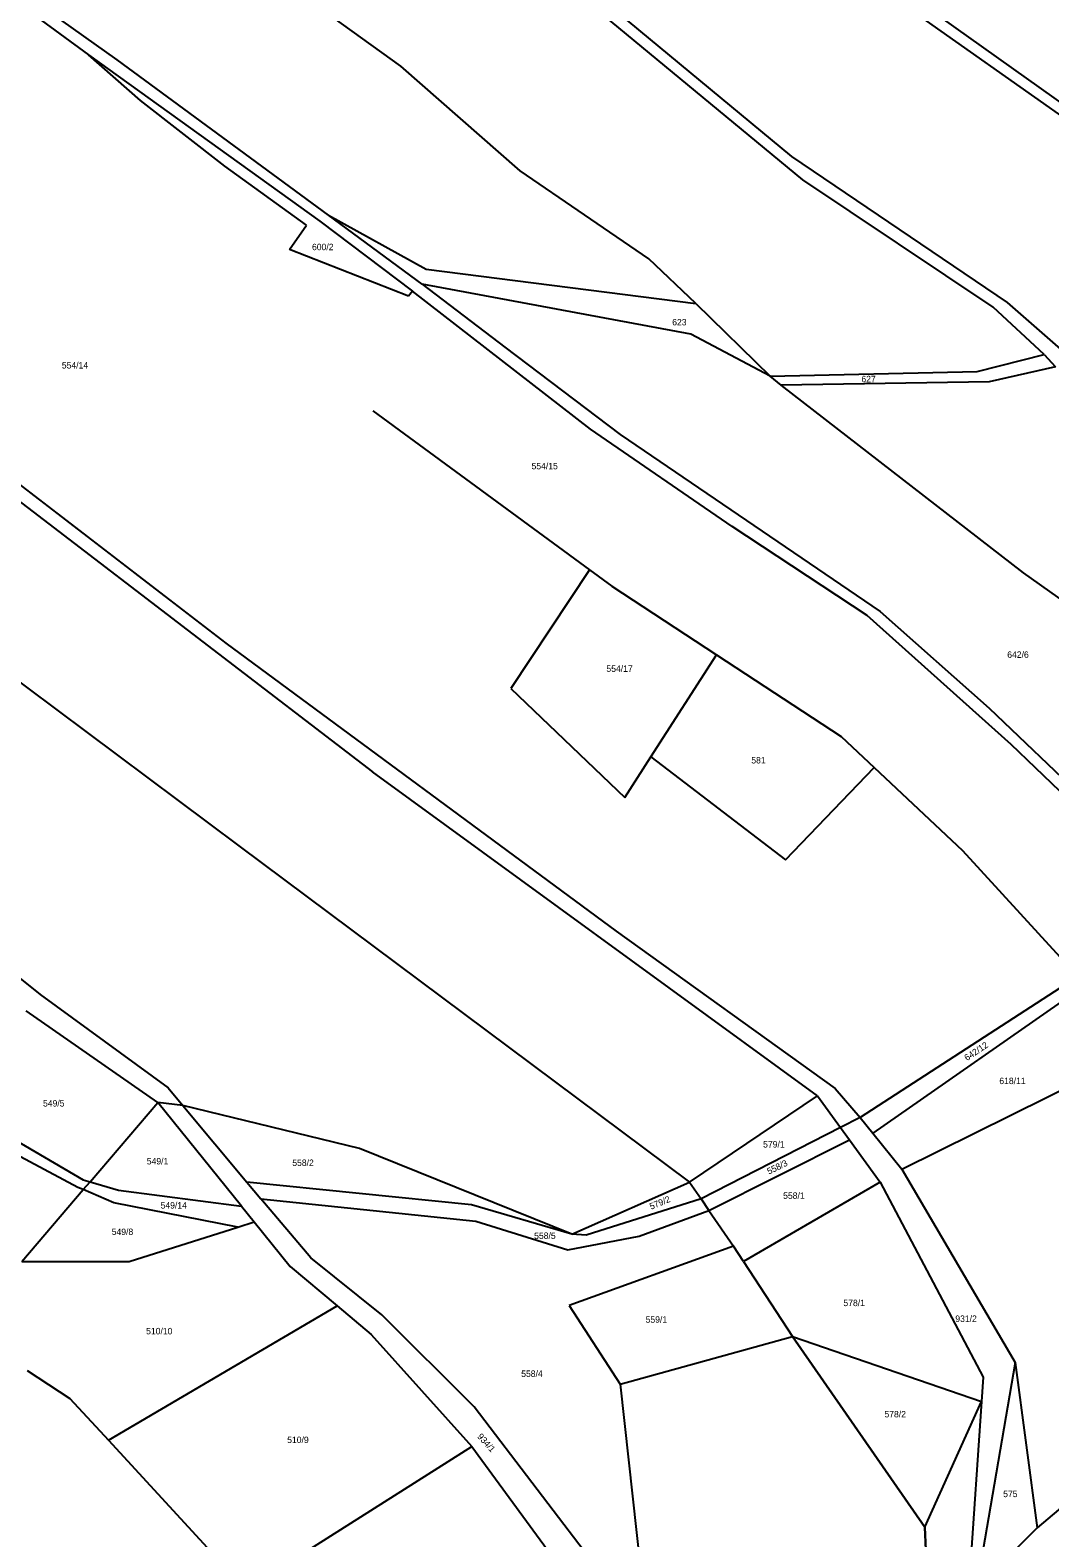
# Model space of a CAD drawing. Extents: x -593358 to -590116, y -1072518 to -1068420.
# Drawn here: x -591318.1 to -591048.4, y -1071622.8 to -1071223.8 of the extents above; entities that cross this region are included whole.
import ezdxf

# ---------------------------------------------------------------- set-up
doc = ezdxf.new("R2010")
doc.units = 0
for name, color, linetype in [('lesy', 7, 'Continuous'), ('Parcela KN', 7, 'Continuous'), ('Parcela ZE', 7, 'Continuous'), ('Parcelní číslo', 7, 'Continuous')]:
    doc.layers.add(name, color=color, linetype=linetype)

msp = doc.modelspace()

# ---------------------------------------------------------------- linework, layer by layer
at = {"layer": 'lesy'}
msp.add_lwpolyline([(-591129.41, -1071549.64), (-591116.49, -1071569.55), (-591081.49, -1071619.93), (-591080.6, -1071640.12), (-591074.27, -1071656.72), (-591050.09, -1071672.8)], dxfattribs=at)
at = {"layer": 'Parcela KN'}
for p, q in [((-591295.06, -1071231.67), (-591426.56, -1071138.15)), ((-591316.46, -1071220.2), (-591302.62, -1071230.31)), ((-591288.86, -1071242.43), (-591302.62, -1071230.31)), ((-591302.62, -1071230.31), (-591241.43, -1071274.4)), ((-591239.21, -1071272.82), (-591295.06, -1071231.67)), ((-591266.55, -1071259.85), (-591288.86, -1071242.43)), ((-591244.96, -1071275.42), (-591266.55, -1071259.85)), ((-591249.53, -1071281.83), (-591244.96, -1071275.42)), ((-591241.43, -1071274.4), (-591216.95, -1071292.85)), ((-591214.39, -1071291), (-591239.21, -1071272.82)), ((-591239.21, -1071272.82), (-591213.35, -1071287.04)), ((-591218.05, -1071294.25), (-591249.53, -1071281.83)), ((-591213.35, -1071287.04), (-591142.01, -1071296.18)), ((-591214.39, -1071291), (-591192.53, -1071307.71)), ((-591143.32, -1071304.27), (-591214.39, -1071291)), ((-591216.95, -1071292.85), (-591218.05, -1071294.25)), ((-591169.9, -1071329.38), (-591216.95, -1071292.85)), ((-591142.01, -1071296.18), (-591122.34, -1071315.38)), ((-591192.53, -1071307.71), (-591162.08, -1071330.84)), ((-591122.34, -1071315.38), (-591143.32, -1071304.27)), ((-591067.64, -1071314.19), (-591049.88, -1071309.61)), ((-591049.88, -1071309.61), (-591046.94, -1071312.91)), ((-591122.34, -1071315.38), (-591067.64, -1071314.19)), ((-591119.47, -1071317.8), (-591122.34, -1071315.38)), ((-591046.94, -1071312.91), (-591064.41, -1071316.85)), ((-591064.41, -1071316.85), (-591119.47, -1071317.8)), ((-591132.39, -1071355.14), (-591169.9, -1071329.38)), ((-591162.08, -1071330.84), (-591093.32, -1071377.7)), ((-591096.76, -1071378.69), (-591132.39, -1071355.14)), ((-591058.67, -1071412.83), (-591096.76, -1071378.69)), ((-591093.32, -1071377.7), (-591064.44, -1071403.25)), ((-591064.44, -1071403.25), (-590999.61, -1071465.32)), ((-591002.01, -1071467.25), (-591058.67, -1071412.83)), ((-591040.99, -1071474.28), (-591098.56, -1071511.54)), ((-591039.55, -1071476.88), (-591095.19, -1071515.74)), ((-591284.34, -1071507.63), (-591319.16, -1071483.34)), ((-591305.47, -1071530.05), (-591366.89, -1071497.44)), ((-591277.68, -1071508.42), (-591284.34, -1071507.63)), ((-591262.21, -1071535), (-591284.34, -1071507.63)), ((-591143.7, -1071528.67), (-591109.83, -1071505.86)), ((-591109.83, -1071505.86), (-591103.79, -1071514.24)), ((-591338.84, -1071507.71), (-591304.1, -1071528.01)), ((-591231.01, -1071519.76), (-591277.68, -1071508.42)), ((-591277.68, -1071508.42), (-591260.75, -1071528.68)), ((-591098.56, -1071511.54), (-591103.79, -1071514.24)), ((-591098.56, -1071511.54), (-591095.19, -1071515.74)), ((-591103.79, -1071514.24), (-591140.65, -1071533.12)), ((-591103.79, -1071514.24), (-591101.41, -1071517.51)), ((-591138.55, -1071536.14), (-591101.41, -1071517.51)), ((-591101.41, -1071517.51), (-591093.27, -1071528.7)), ((-591095.19, -1071515.74), (-591087.56, -1071525.25)), ((-591174.8, -1071542.41), (-591231.01, -1071519.76)), ((-591087.56, -1071525.25), (-591057.55, -1071576.38)), ((-591304.05, -1071530.65), (-591305.47, -1071530.05)), ((-591304.1, -1071528.01), (-591302.25, -1071528.55)), ((-591295.93, -1071534.12), (-591304.05, -1071530.65)), ((-591302.25, -1071528.55), (-591294.72, -1071530.78)), ((-591294.72, -1071530.78), (-591262.21, -1071535)), ((-591201.39, -1071534.67), (-591260.75, -1071528.68)), ((-591260.75, -1071528.68), (-591257.09, -1071533.05)), ((-591174.8, -1071542.41), (-591143.7, -1071528.67)), ((-591093.27, -1071528.7), (-591129.41, -1071549.64)), ((-591093.27, -1071528.7), (-591066.07, -1071580.27)), ((-591263.17, -1071540.57), (-591295.93, -1071534.12)), ((-591262.21, -1071535), (-591258.83, -1071539.2)), ((-591243.84, -1071548.69), (-591257.09, -1071533.05)), ((-591257.09, -1071533.05), (-591200.23, -1071538.99)), ((-591174.8, -1071542.41), (-591201.39, -1071534.67)), ((-591140.65, -1071533.12), (-591171.07, -1071542.73)), ((-591263.17, -1071540.57), (-591258.83, -1071539.2)), ((-591258.83, -1071539.2), (-591249.32, -1071551.02)), ((-591200.23, -1071538.99), (-591175.89, -1071546.61)), ((-591157.04, -1071542.95), (-591138.55, -1071536.14)), ((-591291.88, -1071549.63), (-591263.17, -1071540.57)), ((-591175.89, -1071546.61), (-591157.04, -1071542.95)), ((-591171.07, -1071542.73), (-591174.8, -1071542.41)), ((-591132.05, -1071545.6), (-591175.49, -1071561.31)), ((-591129.41, -1071549.64), (-591132.05, -1071545.6)), ((-591320.29, -1071549.62), (-591291.88, -1071549.63)), ((-591249.32, -1071551.02), (-591236.9, -1071561.42)), ((-591225.05, -1071563.81), (-591243.84, -1071548.69)), ((-591129.41, -1071549.64), (-591116.49, -1071569.55)), ((-590978.58, -1071557.78), (-591051.73, -1071620.17)), ((-591236.9, -1071561.42), (-591227.85, -1071569)), ((-591175.49, -1071561.31), (-591162.02, -1071582.15)), ((-591200.64, -1071588.13), (-591225.05, -1071563.81)), ((-591227.85, -1071569), (-591201.27, -1071598.58)), ((-591162.02, -1071582.15), (-591116.49, -1071569.55)), ((-591116.49, -1071569.55), (-591066.5, -1071586.69)), ((-591081.49, -1071619.93), (-591116.49, -1071569.55)), ((-591057.55, -1071576.38), (-591067.34, -1071633.4)), ((-591057.55, -1071576.38), (-591051.73, -1071620.17)), ((-591162.02, -1071582.15), (-591156.54, -1071631.79)), ((-591066.07, -1071580.27), (-591066.5, -1071586.69)), ((-591081.49, -1071619.93), (-591066.5, -1071586.69)), ((-591066.5, -1071586.69), (-591071.03, -1071653.67)), ((-591154.73, -1071648.38), (-591200.64, -1071588.13)), ((-591201.27, -1071598.58), (-591172.76, -1071637.59)), ((-591080.6, -1071640.12), (-591081.49, -1071619.93)), ((-591051.73, -1071620.17), (-591065.88, -1071634.25))]:
    msp.add_line(p, q, dxfattribs=at)
at = {"layer": 'Parcela ZE'}
for p, q in [((-591220.06, -1071233.35), (-591352.83, -1071137.47)), ((-591195.09, -1071192.29), (-591116.7, -1071257.23)), ((-591113.72, -1071263.44), (-591194.82, -1071196.39)), ((-591104.41, -1071204.86), (-591016.95, -1071266.67)), ((-591016.38, -1071263.81), (-591096.58, -1071206.61)), ((-591188.46, -1071261.08), (-591220.06, -1071233.35)), ((-591116.7, -1071257.23), (-591059.73, -1071295.92)), ((-591154.46, -1071284.37), (-591188.46, -1071261.08)), ((-591063.41, -1071297.16), (-591113.72, -1071263.44)), ((-591142.01, -1071296.18), (-591154.46, -1071284.37)), ((-591059.73, -1071295.92), (-591044.16, -1071309.49)), ((-591049.88, -1071309.61), (-591063.41, -1071297.16)), ((-591362.5, -1071312.09), (-591266.35, -1071386)), ((-591360.73, -1071318.27), (-591317.27, -1071351.25)), ((-591055.39, -1071367.39), (-591119.47, -1071317.8)), ((-591227.42, -1071324.56), (-591170.19, -1071366.63)), ((-591382.66, -1071350.21), (-591262.87, -1071439.67)), ((-591317.27, -1071351.25), (-591227.56, -1071420.07)), ((-591170.19, -1071366.63), (-591191, -1071398.03)), ((-591170.19, -1071366.63), (-591164.27, -1071370.98)), ((-591028.91, -1071386.21), (-591055.39, -1071367.39)), ((-591164.27, -1071370.98), (-591136.59, -1071389.1)), ((-591266.35, -1071386), (-591163.09, -1071462.29)), ((-591153.95, -1071416.15), (-591136.59, -1071389.1)), ((-591136.59, -1071389.1), (-591103.56, -1071410.73)), ((-591191, -1071398.03), (-591160.85, -1071426.9)), ((-591103.56, -1071410.73), (-591094.85, -1071418.94)), ((-591393.82, -1071416.4), (-591315.39, -1071478.99)), ((-591160.85, -1071426.9), (-591153.95, -1071416.15)), ((-591153.95, -1071416.15), (-591118.33, -1071443.4)), ((-591118.33, -1071443.4), (-591094.85, -1071418.94)), ((-591094.85, -1071418.94), (-591071.54, -1071440.92)), ((-591109.83, -1071505.86), (-591227.56, -1071420.07)), ((-591262.87, -1071439.67), (-591143.7, -1071528.67)), ((-591071.54, -1071440.92), (-591040.99, -1071474.28)), ((-591163.09, -1071462.29), (-591105.16, -1071503.86)), ((-591315.39, -1071478.99), (-591281.62, -1071503.75)), ((-591087.56, -1071525.25), (-591026.5, -1071494.92)), ((-591302.25, -1071528.55), (-591284.34, -1071507.63)), ((-591281.62, -1071503.75), (-591277.68, -1071508.42)), ((-591105.16, -1071503.86), (-591098.56, -1071511.54)), ((-591320.29, -1071549.62), (-591304.05, -1071530.65)), ((-591304.05, -1071530.65), (-591302.25, -1071528.55)), ((-591143.7, -1071528.67), (-591140.65, -1071533.12)), ((-591140.65, -1071533.12), (-591138.55, -1071536.14)), ((-591138.55, -1071536.14), (-591132.05, -1071545.6)), ((-591297.38, -1071596.97), (-591236.9, -1071561.42)), ((-591318.88, -1071578.5), (-591307.55, -1071585.92)), ((-591307.55, -1071585.92), (-591297.38, -1071596.97)), ((-591297.38, -1071596.97), (-591261.05, -1071636.45)), ((-591261.05, -1071636.45), (-591201.27, -1071598.58))]:
    msp.add_line(p, q, dxfattribs=at)

# ---------------------------------------------------------------- texts
at = {"layer": 'Parcelní číslo'}
for s, p in [('600/2', (-591243.54, -1071282.05)), ('623', (-591148.275, -1071301.95)), ('554/14', (-591309.698, -1071313.36)), ('627', (-591098.238, -1071316.99)), ('554/15', (-591185.485, -1071340.02)), ('554/17', (-591165.678, -1071393.63)), ('642/6', (-591059.677, -1071389.92)), ('581', (-591127.36, -1071417.87)), ('618/11', (-591061.765, -1071502.72)), ('549/5', (-591314.677, -1071508.66)), ('579/1', (-591124.232, -1071519.51)), ('549/1', (-591287.232, -1071523.98)), ('558/2', (-591248.757, -1071524.38)), ('558/1', (-591118.936, -1071533.08)), ('549/14', (-591283.581, -1071535.65)), ('549/8', (-591296.51, -1071542.65)), ('558/5', (-591184.791, -1071543.69)), ('578/1', (-591102.999, -1071561.47)), ('510/10', (-591287.407, -1071568.93)), ('559/1', (-591155.309, -1071565.87)), ('931/2', (-591073.406, -1071565.65)), ('558/4', (-591188.214, -1071580.2)), ('578/2', (-591092.15, -1071590.91)), ('510/9', (-591250.099, -1071597.71)), ('575', (-591060.748, -1071612.02))]:
    msp.add_text(s, height=1.7, dxfattribs=at).set_placement(p)
for s, rotation, p in [('642/12', 33.63262, (-591070.325, -1071496.662)), ('558/3', 25.95499, (-591122.694, -1071526.683)), ('579/2', 22.63183, (-591153.853, -1071535.992)), ('934/1', 312.2047, (-591199.961, -1071596.09))]:
    msp.add_text(s, height=1.7, rotation=rotation, dxfattribs=at).set_placement(p)

doc.saveas('drawing.dxf')
